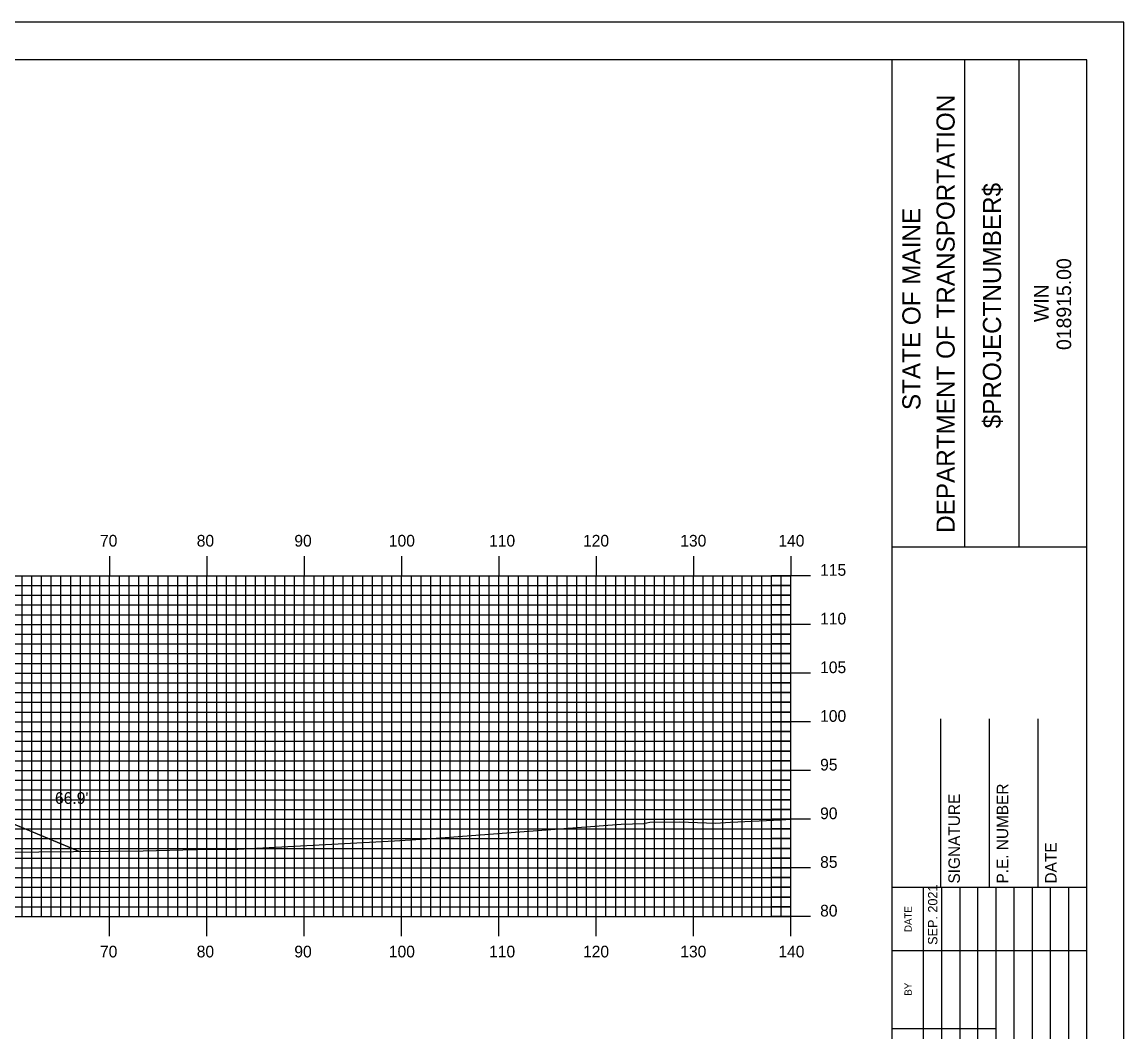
# Model space of a CAD drawing. Extents: x 1761791 to 1762134, y 442591 to 442811.
# Drawn here: x 1762017.8 to 1762131, y 442706.8 to 442810.5 of the extents above; entities that cross this region are included whole.
import ezdxf

# ---------------------------------------------------------------- set-up
doc = ezdxf.new("R2010")
doc.units = 0
for name, color, linetype in [('BORDER', 7, 'Continuous'), ('D_Roadway_Centerline', 7, 'Continuous'), ('D_Roadway_SlopeLines', 7, 'Continuous'), ('D_Text_Standard', 7, 'Continuous'), ('H_V ANNOTATION', 7, 'Continuous'), ('MAJOR', 7, 'Continuous'), ('MINOR', 7, 'Continuous'), ('PLOT BOUNDARY', 7, 'Continuous'), ('S_Roadway_Centerline', 7, 'Continuous')]:
    doc.layers.add(name, color=color, linetype=linetype)

msp = doc.modelspace()

# ---------------------------------------------------------------- linework, layer by layer
at = {"layer": 'BORDER'}
for p, q in [((1762107.15, 442596.67), (1762107.15, 442806.67)), ((1762114.61, 442756.66), (1762114.61, 442806.66)), ((1762120.2, 442756.66), (1762120.2, 442806.66)), ((1762107.15, 442756.65), (1762127.15, 442756.65)), ((1762112.15, 442721.67), (1762112.15, 442738.97)), ((1762117.15, 442721.67), (1762117.15, 442738.97)), ((1762122.15, 442721.67), (1762122.15, 442738.97)), ((1762107.15, 442721.67), (1762127.15, 442721.67))]:
    msp.add_line(p, q, dxfattribs=at)
msp.add_lwpolyline([(1761807.15, 442596.67), (1762127.15, 442596.67), (1762127.15, 442806.67), (1761807.15, 442806.67)], close=True, dxfattribs=at)
for points in [[(1762110.38, 442715.17), (1762110.38, 442721.67)], [(1762112.25, 442686.68), (1762112.25, 442721.67)], [(1762114.11, 442721.67), (1762114.11, 442686.68)], [(1762115.97, 442686.68), (1762115.97, 442721.67)], [(1762117.84, 442686.68), (1762117.84, 442721.67)], [(1762119.7, 442686.68), (1762119.7, 442721.67)], [(1762121.56, 442686.68), (1762121.56, 442721.67)], [(1762123.43, 442686.68), (1762123.43, 442721.67)], [(1762125.29, 442686.68), (1762125.29, 442721.67)], [(1762110.38, 442686.68), (1762110.38, 442720.26)], [(1762107.15, 442715.17), (1762127.15, 442715.17)], [(1762107.15, 442707.17), (1762110.38, 442707.17)], [(1762110.38, 442707.17), (1762117.84, 442707.17)]]:
    msp.add_lwpolyline(points, dxfattribs=at)
at = {"layer": 'D_Roadway_Centerline'}
msp.add_lwpolyline([(1761890.44, 442724.74), (1761927.3, 442740.09), (1761933.75, 442742.78), (1761936.75, 442742.9), (1761936.75, 442742.9), (1761944.75, 442743.22), (1761956.75, 442743.66), (1761967.41, 442744.04), (1761968.75, 442744.09), (1761968.76, 442744.09), (1761976.75, 442743.77), (1761976.76, 442743.77), (1761979.75, 442743.65), (1761985.46, 442741.27), (1761985.5, 442741.25), (1762023.27, 442725.52), (1762023.67, 442725.35)], dxfattribs=at)
at = {"layer": 'D_Roadway_SlopeLines'}
msp.add_lwpolyline([(1761979.75, 442743.65), (1762023.67, 442725.35)], dxfattribs=at)
at = {"layer": 'MAJOR'}
for p, q in [((1762026.75, 442755.67), (1762026.75, 442753.67)), ((1762036.75, 442755.67), (1762036.75, 442753.67)), ((1762046.75, 442755.67), (1762046.75, 442753.67)), ((1762056.75, 442755.67), (1762056.75, 442753.67)), ((1762066.75, 442755.67), (1762066.75, 442753.67)), ((1762076.75, 442755.67), (1762076.75, 442753.67)), ((1762086.75, 442755.67), (1762086.75, 442753.67)), ((1762096.75, 442755.67), (1762096.75, 442753.67)), ((1761816.75, 442753.67), (1762096.75, 442753.67)), ((1761816.75, 442753.67), (1762096.75, 442753.67)), ((1762026.75, 442718.67), (1762026.75, 442753.67)), ((1762036.75, 442718.67), (1762036.75, 442753.67)), ((1762046.75, 442718.67), (1762046.75, 442753.67)), ((1762056.75, 442718.67), (1762056.75, 442753.67)), ((1762066.75, 442718.67), (1762066.75, 442753.67)), ((1762076.75, 442718.67), (1762076.75, 442753.67)), ((1762086.75, 442718.67), (1762086.75, 442753.67)), ((1762098.76, 442753.67), (1762094.75, 442753.67)), ((1762096.75, 442718.67), (1762096.75, 442753.67)), ((1762096.75, 442718.67), (1762096.75, 442753.67)), ((1761816.75, 442748.67), (1762096.75, 442748.67)), ((1762098.76, 442748.67), (1762094.75, 442748.67)), ((1761816.75, 442743.67), (1762096.75, 442743.67)), ((1762098.76, 442743.67), (1762094.75, 442743.67)), ((1761816.75, 442738.67), (1762096.75, 442738.67)), ((1762098.76, 442738.67), (1762094.75, 442738.67)), ((1761816.75, 442733.67), (1762096.75, 442733.67)), ((1762098.76, 442733.67), (1762094.75, 442733.67)), ((1761816.75, 442728.67), (1762096.75, 442728.67)), ((1762098.76, 442728.67), (1762094.75, 442728.67)), ((1761816.75, 442723.67), (1762096.75, 442723.67)), ((1762098.76, 442723.67), (1762094.75, 442723.67)), ((1761816.75, 442718.67), (1762096.75, 442718.67)), ((1761816.75, 442718.67), (1762096.75, 442718.67)), ((1762026.75, 442716.66), (1762026.75, 442718.67)), ((1762036.75, 442716.66), (1762036.75, 442718.67)), ((1762046.75, 442716.66), (1762046.75, 442718.67)), ((1762056.75, 442716.66), (1762056.75, 442718.67)), ((1762066.75, 442716.66), (1762066.75, 442718.67)), ((1762076.75, 442716.66), (1762076.75, 442718.67)), ((1762086.75, 442716.66), (1762086.75, 442718.67)), ((1762098.76, 442718.67), (1762094.75, 442718.67)), ((1762096.75, 442716.66), (1762096.75, 442718.67))]:
    msp.add_line(p, q, dxfattribs=at)
at = {"layer": 'MINOR'}
for p, q in [((1761816.75, 442752.67), (1762096.75, 442752.67)), ((1762017.75, 442718.67), (1762017.75, 442753.67)), ((1762018.75, 442718.67), (1762018.75, 442753.67)), ((1762019.75, 442718.67), (1762019.75, 442753.67)), ((1762020.75, 442718.67), (1762020.75, 442753.67)), ((1762021.75, 442718.67), (1762021.75, 442753.67)), ((1762022.75, 442718.67), (1762022.75, 442753.67)), ((1762023.75, 442718.67), (1762023.75, 442753.67)), ((1762024.75, 442718.67), (1762024.75, 442753.67)), ((1762025.75, 442718.67), (1762025.75, 442753.67)), ((1762027.75, 442718.67), (1762027.75, 442753.67)), ((1762028.75, 442718.67), (1762028.75, 442753.67)), ((1762029.75, 442718.67), (1762029.75, 442753.67)), ((1762030.75, 442718.67), (1762030.75, 442753.67)), ((1762031.75, 442718.67), (1762031.75, 442753.67)), ((1762032.75, 442718.67), (1762032.75, 442753.67)), ((1762033.75, 442718.67), (1762033.75, 442753.67)), ((1762034.75, 442718.67), (1762034.75, 442753.67)), ((1762035.75, 442718.67), (1762035.75, 442753.67)), ((1762037.75, 442718.67), (1762037.75, 442753.67)), ((1762038.75, 442718.67), (1762038.75, 442753.67)), ((1762039.75, 442718.67), (1762039.75, 442753.67)), ((1762040.75, 442718.67), (1762040.75, 442753.67)), ((1762041.75, 442718.67), (1762041.75, 442753.67)), ((1762042.75, 442718.67), (1762042.75, 442753.67)), ((1762043.75, 442718.67), (1762043.75, 442753.67)), ((1762044.75, 442718.67), (1762044.75, 442753.67)), ((1762045.75, 442718.67), (1762045.75, 442753.67)), ((1762047.75, 442718.67), (1762047.75, 442753.67)), ((1762048.75, 442718.67), (1762048.75, 442753.67)), ((1762049.75, 442718.67), (1762049.75, 442753.67)), ((1762050.75, 442718.67), (1762050.75, 442753.67)), ((1762051.75, 442718.67), (1762051.75, 442753.67)), ((1762052.75, 442718.67), (1762052.75, 442753.67)), ((1762053.75, 442718.67), (1762053.75, 442753.67)), ((1762054.75, 442718.67), (1762054.75, 442753.67)), ((1762055.75, 442718.67), (1762055.75, 442753.67)), ((1762057.75, 442718.67), (1762057.75, 442753.67)), ((1762058.75, 442718.67), (1762058.75, 442753.67)), ((1762059.75, 442718.67), (1762059.75, 442753.67)), ((1762060.75, 442718.67), (1762060.75, 442753.67)), ((1762061.75, 442718.67), (1762061.75, 442753.67)), ((1762062.75, 442718.67), (1762062.75, 442753.67)), ((1762063.75, 442718.67), (1762063.75, 442753.67)), ((1762064.75, 442718.67), (1762064.75, 442753.67)), ((1762065.75, 442718.67), (1762065.75, 442753.67)), ((1762067.75, 442718.67), (1762067.75, 442753.67)), ((1762068.75, 442718.67), (1762068.75, 442753.67)), ((1762069.75, 442718.67), (1762069.75, 442753.67)), ((1762070.75, 442718.67), (1762070.75, 442753.67)), ((1762071.75, 442718.67), (1762071.75, 442753.67)), ((1762072.75, 442718.67), (1762072.75, 442753.67)), ((1762073.75, 442718.67), (1762073.75, 442753.67)), ((1762074.75, 442718.67), (1762074.75, 442753.67)), ((1762075.75, 442718.67), (1762075.75, 442753.67)), ((1762077.75, 442718.67), (1762077.75, 442753.67)), ((1762078.75, 442718.67), (1762078.75, 442753.67)), ((1762079.75, 442718.67), (1762079.75, 442753.67)), ((1762080.75, 442718.67), (1762080.75, 442753.67)), ((1762081.75, 442718.67), (1762081.75, 442753.67)), ((1762082.75, 442718.67), (1762082.75, 442753.67)), ((1762083.75, 442718.67), (1762083.75, 442753.67)), ((1762084.75, 442718.67), (1762084.75, 442753.67)), ((1762085.75, 442718.67), (1762085.75, 442753.67)), ((1762087.75, 442718.67), (1762087.75, 442753.67)), ((1762088.75, 442718.67), (1762088.75, 442753.67)), ((1762089.75, 442718.67), (1762089.75, 442753.67)), ((1762090.75, 442718.67), (1762090.75, 442753.67)), ((1762091.75, 442718.67), (1762091.75, 442753.67)), ((1762092.75, 442718.67), (1762092.75, 442753.67)), ((1762093.75, 442718.67), (1762093.75, 442753.67)), ((1762094.75, 442718.67), (1762094.75, 442753.67)), ((1762096.75, 442752.67), (1762094.75, 442752.67)), ((1762095.75, 442718.67), (1762095.75, 442753.67)), ((1761816.75, 442751.67), (1762096.75, 442751.67)), ((1762096.75, 442751.67), (1762094.75, 442751.67)), ((1761816.75, 442750.67), (1762096.75, 442750.67)), ((1762096.75, 442750.67), (1762094.75, 442750.67)), ((1761816.75, 442749.67), (1762096.75, 442749.67)), ((1762096.75, 442749.67), (1762094.75, 442749.67)), ((1761816.75, 442747.67), (1762096.75, 442747.67)), ((1762096.75, 442747.67), (1762094.75, 442747.67)), ((1761816.75, 442746.67), (1762096.75, 442746.67)), ((1762096.75, 442746.67), (1762094.75, 442746.67)), ((1761816.75, 442745.67), (1762096.75, 442745.67)), ((1761816.75, 442744.67), (1762096.75, 442744.67)), ((1762096.75, 442745.67), (1762094.75, 442745.67)), ((1762096.75, 442744.67), (1762094.75, 442744.67)), ((1761816.75, 442742.67), (1762096.75, 442742.67)), ((1762096.75, 442742.67), (1762094.75, 442742.67)), ((1761816.75, 442741.67), (1762096.75, 442741.67)), ((1762096.75, 442741.67), (1762094.75, 442741.67)), ((1761816.75, 442740.67), (1762096.75, 442740.67)), ((1762096.75, 442740.67), (1762094.75, 442740.67)), ((1761816.75, 442739.67), (1762096.75, 442739.67)), ((1762096.75, 442739.67), (1762094.75, 442739.67)), ((1761816.75, 442737.67), (1762096.75, 442737.67)), ((1762096.75, 442737.67), (1762094.75, 442737.67)), ((1761816.75, 442736.67), (1762096.75, 442736.67)), ((1761816.75, 442735.67), (1762096.75, 442735.67)), ((1762096.75, 442736.67), (1762094.75, 442736.67)), ((1762096.75, 442735.67), (1762094.75, 442735.67)), ((1761816.75, 442734.67), (1762096.75, 442734.67)), ((1762096.75, 442734.67), (1762094.75, 442734.67)), ((1761816.75, 442732.67), (1762096.75, 442732.67)), ((1762096.75, 442732.67), (1762094.75, 442732.67)), ((1761816.75, 442731.67), (1762096.75, 442731.67)), ((1762096.75, 442731.67), (1762094.75, 442731.67)), ((1761816.75, 442730.67), (1762096.75, 442730.67)), ((1762096.75, 442730.67), (1762094.75, 442730.67)), ((1761816.75, 442729.67), (1762096.75, 442729.67)), ((1762096.75, 442729.67), (1762094.75, 442729.67)), ((1761816.75, 442727.67), (1762096.75, 442727.67)), ((1762096.75, 442727.67), (1762094.75, 442727.67)), ((1761816.75, 442726.67), (1762096.75, 442726.67)), ((1762096.75, 442726.67), (1762094.75, 442726.67)), ((1761816.75, 442725.67), (1762096.75, 442725.67)), ((1762096.75, 442725.67), (1762094.75, 442725.67)), ((1761816.75, 442724.67), (1762096.75, 442724.67)), ((1762096.75, 442724.67), (1762094.75, 442724.67)), ((1761816.75, 442722.67), (1762096.75, 442722.67)), ((1762096.75, 442722.67), (1762094.75, 442722.67)), ((1761816.75, 442721.67), (1762096.75, 442721.67)), ((1762096.75, 442721.67), (1762094.75, 442721.67)), ((1761816.75, 442720.67), (1762096.75, 442720.67)), ((1762096.75, 442720.67), (1762094.75, 442720.67)), ((1761816.75, 442719.67), (1762096.75, 442719.67)), ((1762096.75, 442719.67), (1762094.75, 442719.67))]:
    msp.add_line(p, q, dxfattribs=at)
at = {"layer": 'PLOT BOUNDARY'}
msp.add_lwpolyline([(1761790.97, 442590.55), (1762130.97, 442590.55), (1762130.97, 442810.55), (1761790.97, 442810.55)], close=True, dxfattribs=at)
at = {"layer": 'S_Roadway_Centerline'}
msp.add_lwpolyline([(1762012.3, 442725.23), (1762030.19, 442725.42), (1762035.65, 442725.54), (1762039.91, 442725.59), (1762056.03, 442726.45), (1762058.21, 442726.57), (1762059.87, 442726.68), (1762079.3, 442728.14), (1762081.64, 442728.21), (1762082.25, 442728.36), (1762085.29, 442728.41), (1762088.99, 442728.26), (1762090.55, 442728.36), (1762095.72, 442728.61), (1762096.75, 442728.68)], dxfattribs=at)

# ---------------------------------------------------------------- texts
at = {"layer": 'BORDER'}
for s, height, p in [('DEPARTMENT OF TRANSPORTATION', 1.8635, (1762113.57, 442758.08)), ('$PROJECTNUMBER$', 1.8635, (1762118.34, 442768.82)), ('STATE OF MAINE', 1.8635, (1762110.06, 442770.69)), ('018915.00', 1.491, (1762125.54, 442776.86)), ('WIN', 1.491, (1762123.23, 442779.73)), ('P.E. NUMBER', 1.1811, (1762119.07, 442722.06)), ('SIGNATURE', 1.181, (1762114.11, 442722.06)), ('DATE', 1.181, (1762124.04, 442722.06)), ('SEP. 2021', 0.969, (1762111.8, 442715.76)), ('DATE', 0.743, (1762109.16, 442717.08)), ('BY', 0.743, (1762109.16, 442710.54))]:
    msp.add_text(s, height=height, rotation=90, dxfattribs=at).set_placement(p)
at = {"layer": 'D_Text_Standard'}
msp.add_text("66.9'", height=1.2, dxfattribs=at).set_placement((1762021.14, 442730.24))
at = {"layer": 'H_V ANNOTATION'}
for s, p in [('70', (1762025.76, 442756.67)), ('80', (1762035.7, 442756.67)), ('90', (1762045.73, 442756.67)), ('100', (1762055.44, 442756.67)), ('110', (1762065.74, 442756.67)), ('120', (1762075.39, 442756.67)), ('130', (1762085.38, 442756.67)), ('140', (1762095.46, 442756.67)), ('115', (1762099.75, 442753.67)), ('110', (1762099.75, 442748.67)), ('105', (1762099.75, 442743.67)), ('100', (1762099.75, 442738.67)), ('95', (1762099.75, 442733.67)), ('90', (1762099.75, 442728.67)), ('85', (1762099.75, 442723.67)), ('80', (1762099.75, 442718.67)), ('70', (1762025.76, 442714.47)), ('80', (1762035.7, 442714.47)), ('90', (1762045.73, 442714.47)), ('100', (1762055.44, 442714.47)), ('110', (1762065.74, 442714.47)), ('120', (1762075.39, 442714.47)), ('130', (1762085.38, 442714.47)), ('140', (1762095.46, 442714.47))]:
    msp.add_text(s, height=1.2, dxfattribs=at).set_placement(p)

doc.saveas('drawing.dxf')
